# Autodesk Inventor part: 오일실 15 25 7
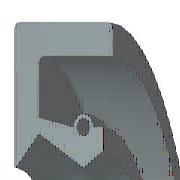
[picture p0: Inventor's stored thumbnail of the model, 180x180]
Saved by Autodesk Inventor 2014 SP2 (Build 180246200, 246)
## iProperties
Created: 2012-02
Part Number: 오일실 15 25 7
Material: 고무
Description: 오일-실
Document SubType Name: Modeling
Standard: KS B 2804
Designer: mduedu
Standards Organization: KS
Language: ko-KR
Size Designation: D - 15 25 7
Categories: <MemberInstance><Categories><Category DisplayName="샤프트 부품" InternalName="7f7aeb1f-a693-4053-b835-cee3144e0d98" Mnemonic="SHFT"><Category DisplayName="실링" Intern
Density: 0.93 g/cm^3
Appearance: 고무 - 검은색 - 버전 1.1
IsCustomPart: 1
Author: mduedu
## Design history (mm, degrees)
revolve "본체" stored, may be unused: angle "d17" = 90 deg
revolve "스프링1" stored, may be unused: angle "d18" = 90 deg
body "Solid1"
sketch "스케치1"
  geometry: L1 (0, 12.5)-(7, 12.5); L2 (7, 10.75)-(1.75, 10.75); L3 (1.75, 9.25)-(4.9, 7.5); L4 (4.9, 7.5)-(0, 7.5); L5 (0, 0)-(9.586, 0) reference; L6 (4.9, 7.5)-(6.3, 8.375); L7 (0, 18)-(0, -3) reference; L8 (-1.941, 0)-(11.507, 0) reference; L9 (4.2, 9.6)-(1.75, 10.09); L10 (1.75, 10.09)-(1.75, 10.75); L11 (0, 12.5)-(0, 7.588); L12 (4.9, 7.5)-(0, 7.5); L13 (1.75, 9.25)-(0.152, 7.528); L14 (7, 12.5)-(7, 10.75); L15 (5.6, 9.6)-(6.3, 9.6); L16 (6.3, 9.6)-(6.3, 8.375); C1 r 0.455 at (4.9, 9.6); A1 r 0.7 centre (4.9, 9.6) between (5.6, 9.6) and (4.2, 9.6); A2 r 0.088 centre (0.088, 7.588) between (0, 7.588) and (0.152, 7.528); 1 further point
  constraints: 28 end point, 5 horizontal alignment, 5 point on line, 4 point on circle, 4 vertical alignment, 3 centre point, 3 tangent, 2 collinear, 2 horizontal, 2 perpendicular, 1 coincident, 1 parallel
  dimensions: "d0" = 25 diameter of L1 L5 (= SD2); "d1" = 1.75 distance of L1.end L2.start (= SD); "d2" = 0.91 diameter of C1 (= SPDI); "d3" = 1.4 diameter of A1 (= SPDA); "d4" = 15 diameter of L3.end L5 (= NND); "d5" = 18.5 diameter of L3.start L5 (= TKDM); "d7" = 20.18 diameter of L9.end L5 (= TKDM + 0.24 x SWDT); "d8" = 1.75 distance between parallel lines of L11 L10 (= SD); "d9" = 4.9 distance from line of L11 C1.centre (= SPDST); "d10" = 19.2 diameter of C1.centre L5 (= HLDM); "d11" = 0.0875 radius of A2 (= 0.25 x LAB); "d12" = 6.3 distance between parallel lines of L11 L16 (= SDI); "d13" = 16.75 diameter of L6.end L5 (= ABDM); "d14" = 7 distance from line of L11 L1.end (= SWDT)
fillet "모깎기1" dims "d6" = 0.3 (= RR)
other parameters: "SD2" = 25 [user parameter; used in 1 equation term], "SWDT" = 7 [user parameter; used in 2 equation terms], "RR" = 0.3 [user parameter; used in 1 equation term], "SD" = 1.75 [user parameter; used in 2 equation terms], "NND" = 15 [user parameter; used in 1 equation term], "SPDA" = 1.4 [user parameter; used in 1 equation term], "SPDI" = 0.91 [user parameter; used in 1 equation term], "TKDM" = 18.5 [user parameter; used in 2 equation terms], "HLDM" = 19.2 [user parameter; used in 1 equation term], "ABDM" = 16.75 [user parameter; used in 1 equation term], "SDI" = 6.3 [user parameter; used in 1 equation term], "SPDST" = 4.9 [user parameter; used in 1 equation term], "LAB" = 0.35 [user parameter; used in 1 equation term], "d15" = 0, "d16" = 0, "d19" = 0
